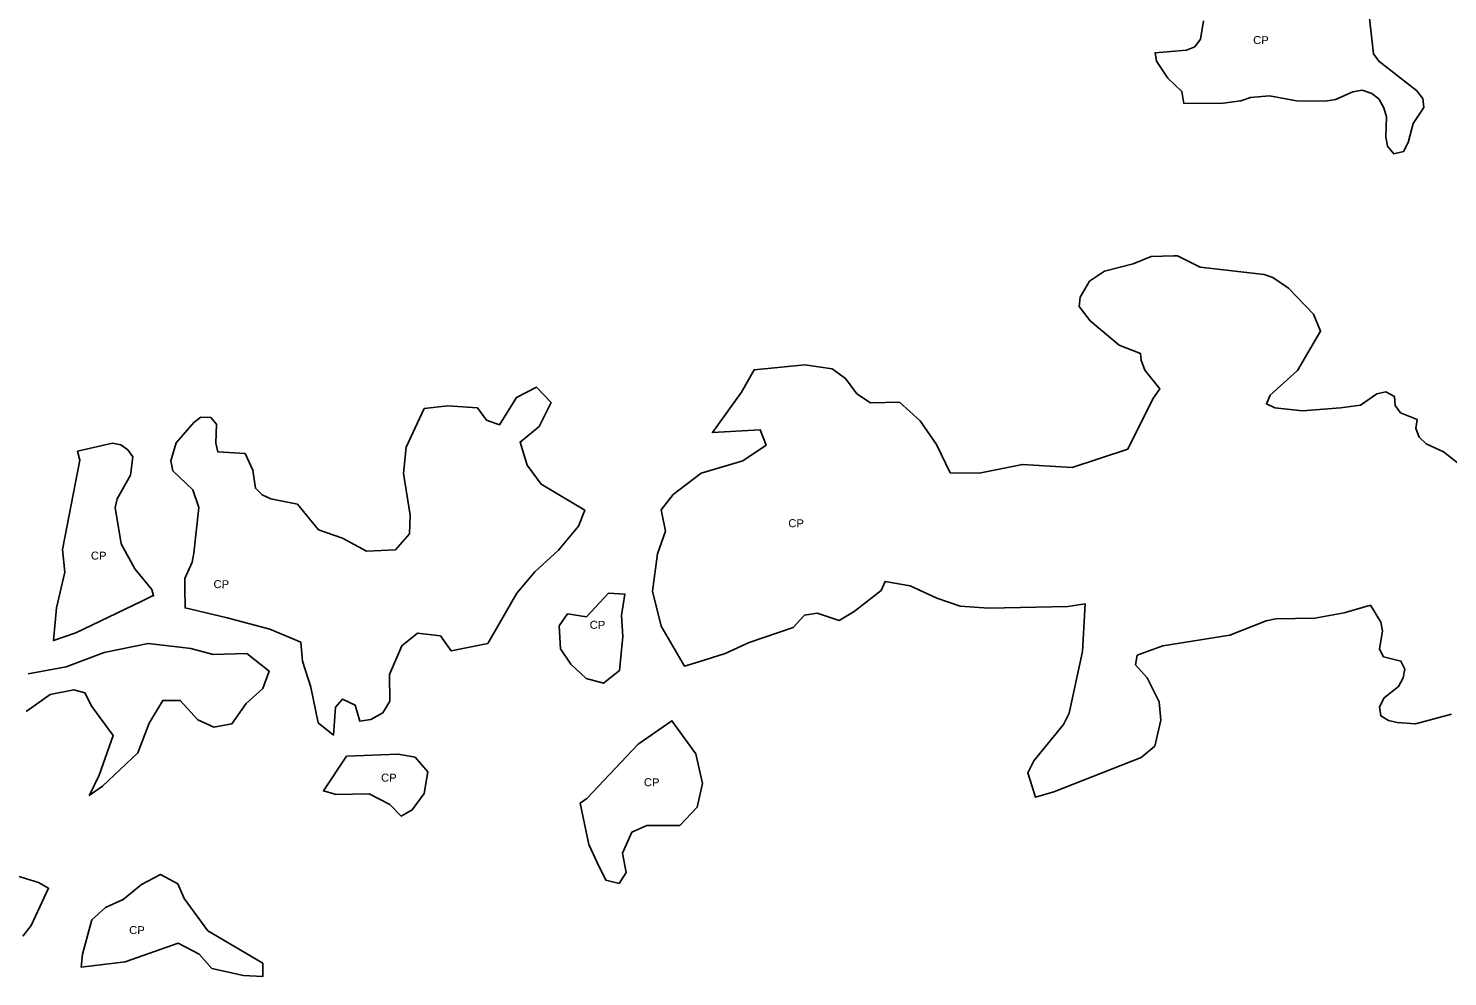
# Model space of a CAD drawing. Extents: x 713589 to 726391, y 7177764 to 7191819.
# Drawn here: x 723901 to 725036, y 7188137 to 7188896 of the extents above; entities that cross this region are included whole.
import ezdxf
from ezdxf.enums import TextEntityAlignment as Align

# ---------------------------------------------------------------- set-up
doc = ezdxf.new("R2010")
doc.units = 0
doc.header["$LTSCALE"] = 2.6
doc.layers.add('63', color=7, linetype='Continuous', lineweight=25)

msp = doc.modelspace()

# ---------------------------------------------------------------- linework, layer by layer
at = {"layer": '63'}
for points in [[(724840.66, 7188902.14), (724838.34, 7188887.28), (724833.72, 7188881.34), (724827.11, 7188878.7), (724802.02, 7188876.52), (724803.26, 7188869.86), (724812.12, 7188856.32), (724823.54, 7188845.67), (724824.89, 7188836), (724856.49, 7188836.09), (724870.7, 7188838.07), (724878.29, 7188840.71), (724893.48, 7188842.03), (724915.28, 7188838.06), (724938.07, 7188837.73), (724946.32, 7188839.04), (724960.19, 7188845.32), (724967.79, 7188846.64), (724975.38, 7188843.99), (724981, 7188839.7), (724984.96, 7188832.43), (724987.27, 7188825.17), (724986.61, 7188809.31), (724987.93, 7188801.72), (724992.88, 7188795.77), (725000.8, 7188797.42), (725004.44, 7188804.69), (725008.4, 7188819.88), (725016.99, 7188832.75), (725016.33, 7188840.02), (725011.05, 7188846.3), (724981, 7188869.75), (724976.71, 7188875.7), (724972.43, 7188913.67)], [(725045, 7188547.75), (725032.79, 7188557.33), (725018.92, 7188563.6), (725013.3, 7188568.89), (725010.66, 7188575.82), (725011.66, 7188583.09), (724998.45, 7188588.38), (724994.16, 7188594.32), (724993.5, 7188601.59), (724986.56, 7188605.22), (724979.3, 7188603.57), (724966.41, 7188594.66), (724950.23, 7188592.35), (724919.85, 7188590.04), (724897.72, 7188592.36), (724891.12, 7188595.67), (724894.09, 7188602.6), (724915.89, 7188622.41), (724934.39, 7188653.78), (724928.78, 7188667.32), (724908.64, 7188688.13), (724896.09, 7188696.72), (724889.16, 7188699.03), (724837.97, 7188704.99), (724820, 7188714.02), (724817.09, 7188713.95), (724799.01, 7188713.58), (724784.47, 7188707.64), (724761.68, 7188701.7), (724749.46, 7188693.78), (724742.2, 7188680.9), (724741.2, 7188673.64), (724750.12, 7188662.07), (724773.23, 7188642.59), (724790.26, 7188635.97), (724790.85, 7188630.69), (724793.9, 7188622.51), (724805.81, 7188607.8), (724800.3, 7188599.65), (724780.15, 7188559.36), (724735.56, 7188544.84), (724695.93, 7188547.16), (724661.26, 7188540.23), (724638.14, 7188540.57), (724627.24, 7188563.03), (724614.04, 7188582.18), (724597.53, 7188597.05), (724574.41, 7188596.39), (724563.52, 7188603.66), (724554.27, 7188615.88)], [(724554.27, 7188615.88), (724543.71, 7188623.81), (724521.91, 7188626.79), (724481.29, 7188622.83), (724471.05, 7188605), (724447.92, 7188572.64), (724486.23, 7188574.95), (724490.85, 7188562.73), (724472.36, 7188550.18), (724439, 7188540.28), (724416.54, 7188523.11), (724406.96, 7188510.9), (724410.26, 7188493.72), (724403.98, 7188475.56), (724400.01, 7188445.84), (724406.94, 7188417.77), (724425.56, 7188385.84), (724436.94, 7188389.38), (724458.12, 7188395.96), (724477.28, 7188404.87), (724512.62, 7188416.75), (724521.54, 7188426.66), (724531.77, 7188428.31), (724549.28, 7188422.36), (724561.17, 7188429.62), (724582.97, 7188446.46), (724586.02, 7188453.57), (724606.08, 7188450.09), (724627.55, 7188440.18), (724646.04, 7188433.9), (724669.16, 7188432.24), (724732.24, 7188433.55), (724746.14, 7188435.63), (724744.05, 7188397.66), (724733.3, 7188348.16), (724728.67, 7188339.24), (724704.96, 7188310.07), (724700.19, 7188300.41), (724706.44, 7188280.98), (724720.98, 7188285.27), (724790.99, 7188312.67), (724801.89, 7188321.91), (724806.52, 7188342.71), (724805.2, 7188357.25), (724795.63, 7188376.4), (724786.39, 7188386.97), (724787.71, 7188394.57), (724808.19, 7188402.16), (724861.69, 7188410.73)], [(724861.69, 7188410.73), (724890.75, 7188421.96), (724898.68, 7188423.61), (724929.72, 7188424.26), (724953.17, 7188428.55), (724974.31, 7188434.49), (724982.56, 7188420.95), (724983.88, 7188414.01), (724981.56, 7188399.48), (724984.86, 7188393.2), (724998.73, 7188389.9), (725001.71, 7188383.29), (725000.38, 7188376.36), (724996.75, 7188369.42), (724985.19, 7188360.51), (724981.55, 7188353.24), (724982.54, 7188345.98), (724988.82, 7188342.35), (724995.75, 7188340.69), (725010.28, 7188339.7), (725039.02, 7188347.29)], [(723899.01, 7188349.52), (723918.16, 7188363.05), (723936.99, 7188367.01), (723945.9, 7188364.37), (723951.52, 7188353.47), (723968.6, 7188330.37), (723957.36, 7188298.62), (723949.57, 7188282.51), (723949.4, 7188282.34), (723960.09, 7188289.73), (723988.17, 7188316.47), (723997.42, 7188340.25), (724008.32, 7188358.41), (724022.19, 7188358.41), (724036.39, 7188342.88), (724048.94, 7188336.93), (724063.47, 7188339.57), (724075.03, 7188356.08), (724088.24, 7188367.97), (724093.2, 7188381.84), (724075.37, 7188396.04), (724048.62, 7188395.06), (724030.79, 7188400.01), (724021.91, 7188401.04), (723996.44, 7188403.98), (723961.43, 7188396.73), (723931.05, 7188385.17), (723900.66, 7188379.57)], [(723896.33, 7188169.86), (723902.93, 7188178.45), (723916.81, 7188208.17), (723908.88, 7188212.79), (723891.55, 7188217.99)]]:
    msp.add_lwpolyline(points, dxfattribs=at)
for points in [[(724260.02, 7188592.5), (724236.24, 7188594.15), (724217.42, 7188591.85), (724202.88, 7188561.14), (724200.89, 7188540), (724206.17, 7188506.65), (724205.51, 7188491.79), (724194.27, 7188478.91), (724171.16, 7188477.92), (724152, 7188488.16), (724132.85, 7188494.77), (724116.05, 7188515.36), (724113.35, 7188515.89), (724094.55, 7188519.55), (724087.61, 7188522.85), (724082.33, 7188528.14), (724080.35, 7188542.67), (724074.08, 7188555.88), (724052.29, 7188557.21), (724050.64, 7188564.14), (724051.3, 7188579.33), (724046.68, 7188584.62), (724038.75, 7188584.95), (724033.14, 7188580.66), (724018.93, 7188564.48), (724014.64, 7188549.95), (724016.29, 7188542.02), (724032.13, 7188526.83), (724037.08, 7188512.63), (724033.11, 7188476.3), (724031.79, 7188469.04), (724025.84, 7188455.83), (724025.89, 7188448.45), (724026, 7188432.45), (724059.85, 7188424.45), (724093.87, 7188415.52), (724118.63, 7188404.95), (724119.95, 7188389.76), (724126.55, 7188368.95), (724132.49, 7188340.55), (724144.71, 7188330.64), (724146.36, 7188353.09), (724151.98, 7188359.37), (724162.21, 7188354.74), (724165.84, 7188341.86), (724174.76, 7188343.18), (724184.34, 7188348.46), (724189.95, 7188357.71), (724189.63, 7188379.17), (724199.51, 7188402.21), (724212.09, 7188412.19), (724230.26, 7188410.21), (724238.84, 7188397.99), (724268.23, 7188403.93), (724291.36, 7188444.21), (724305.89, 7188461.38), (724324.72, 7188478.55), (724340.91, 7188497.7), (724345.86, 7188510.58), (724310.86, 7188531.39), (724299.64, 7188546.59), (724294.03, 7188565.08), (724309.22, 7188577.63), (724318.8, 7188596.78), (724307.25, 7188609), (724291.06, 7188600.75), (724277.52, 7188578.95), (724267.28, 7188582.59)], [(723982.27, 7188538.73), (723971.7, 7188519.58), (723970.04, 7188512.64), (723974.99, 7188483.58), (723985.89, 7188463.76), (723999.42, 7188447.25), (724000.84, 7188442.1), (724000.08, 7188441.96), (723990.84, 7188437.54), (723938.65, 7188412.58), (723920.71, 7188406.29), (723923.13, 7188432.4), (723929.74, 7188461.13), (723927.89, 7188479.26), (723941.98, 7188550.63), (723940.09, 7188557.73), (723968.07, 7188564.16), (723974.68, 7188562.84), (723980.29, 7188558.87), (723984.25, 7188553.26)], [(724326.36, 7188399.62), (724325.37, 7188418.11), (724331.98, 7188427.69), (724347.17, 7188425.38), (724364.67, 7188444.2), (724377.9, 7188443.5), (724375.24, 7188426.36), (724376.22, 7188409.52), (724373.58, 7188382.44), (724360.7, 7188372.2), (724346.83, 7188375.84), (724334.61, 7188387.4)], [(724421.77, 7188258.25), (724435.64, 7188273.11), (724439.94, 7188291.94), (724434.66, 7188315.71), (724415.45, 7188342.17), (724388.43, 7188323.32), (724347.47, 7188280.07), (724342.24, 7188276.16), (724349.11, 7188243.08), (724355.71, 7188228.88), (724362.64, 7188214.67), (724373.21, 7188212.03), (724378.83, 7188220.62), (724375.86, 7188236.14), (724383.46, 7188252.98), (724395.35, 7188258.26)], [(724173.43, 7188283.74), (724189.94, 7188275.15), (724198.85, 7188265.9), (724207.77, 7188270.85), (724217.35, 7188284.06), (724220.13, 7188301.41), (724210.09, 7188313.12), (724196.55, 7188315.44), (724155.27, 7188313.79), (724136.77, 7188286.06), (724147.01, 7188283.08)], [(724088.19, 7188148.35), (724044.28, 7188174.12), (724025.46, 7188199.89), (724020.18, 7188211.78), (724006.31, 7188219.04), (723991.12, 7188211.12), (723976.58, 7188199.24), (723962.38, 7188192.63), (723951.59, 7188182.81), (723943.88, 7188155.32), (723942.89, 7188145.08), (723978.22, 7188149.37), (724020.5, 7188164.22), (724037.34, 7188155.3), (724047.57, 7188144.07), (724072.67, 7188138.45), (724088.19, 7188137.46)]]:
    msp.add_lwpolyline(points, close=True, dxfattribs=at)

# ---------------------------------------------------------------- texts
at = {"layer": '63', "width": 1.05}
for p in [(724886.65, 7188883.44), (724514.79, 7188496.95), (723956.88, 7188471.03), (724054.99, 7188448.2), (724355.92, 7188415.66), (724189.05, 7188293.39), (724399.27, 7188289.73), (723987.5, 7188171.47)]:
    msp.add_text('CP', height=6.4, rotation=359.062, dxfattribs=at).set_placement(p, align=Align.CENTER)

doc.saveas('drawing.dxf')
